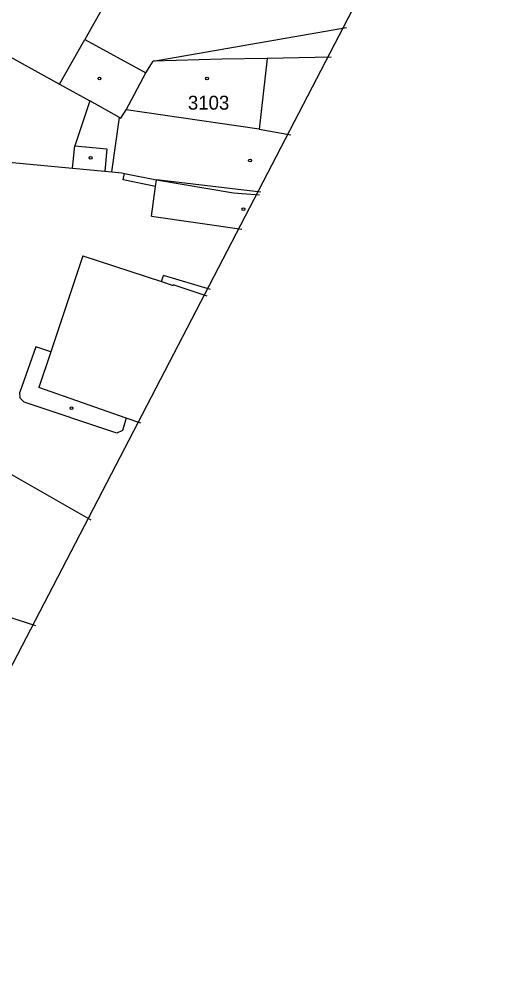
# Model space of a CAD drawing. Extents: x -781083 to -763634, y -1029516 to -1022695.
# Drawn here: x -764957.7 to -764898.4, y -1023999.1 to -1023880.9 of the extents above; entities that cross this region are included whole.
import ezdxf

# ---------------------------------------------------------------- set-up
doc = ezdxf.new("R2010")
doc.units = 0
for name, color, linetype in [('Hranice parcel', 7, 'Continuous'), ('Parcelní čísla', 7, 'Continuous'), ('Vnitřní kresba', 7, 'Continuous'), ('Vrstva 3', 7, 'Continuous'), ('Značky budov', 7, 'Continuous')]:
    doc.layers.add(name, color=color, linetype=linetype)

# ---------------------------------------------------------------- blocks, each defined once
blk = doc.blocks.new('4.02')
at = {"layer": 'Značky budov'}
blk.add_circle((-0.1, 0), 1.75, dxfattribs=at)

msp = doc.modelspace()

# ---------------------------------------------------------------- linework, layer by layer
msp.add_lwpolyline([(-765336.12, -1024363.48), (-765204.05, -1024432.09), (-764769.73, -1023596.11), (-764901.79, -1023527.49)], close=True)
at = {"layer": 'Hranice parcel'}
msp.add_line((-764941.38, -1023885.98), (-764917.77, -1023881.89), dxfattribs=at)
for points in [[(-764927.47, -1023885.67), (-764928.44, -1023894.28), (-764933.48, -1023893.55), (-764944.68, -1023891.94)], [(-764944.68, -1023891.94), (-764942.27, -1023887.42), (-764941.38, -1023885.98)], [(-764927.47, -1023885.67), (-764932.94, -1023885.75), (-764941.38, -1023885.98)], [(-764919.64, -1023885.49), (-764927.47, -1023885.67)], [(-764946.42, -1023899.52), (-764945.51, -1023892.86), (-764945.34, -1023892.96), (-764944.68, -1023891.94)], [(-764967.7, -1023897.5), (-764951.22, -1023899.07), (-764947.29, -1023899.44), (-764946.42, -1023899.52)], [(-764946.42, -1023899.52), (-764945.2, -1023899.64), (-764944.87, -1023899.7), (-764940.96, -1023900.48), (-764931.58, -1023902.07), (-764928.39, -1023902.32)]]:
    msp.add_lwpolyline(points, dxfattribs=at)
at = {"layer": 'Vnitřní kresba'}
for p, q in [((-764944.52, -1023874.04), (-764949.74, -1023883.33)), ((-764963.43, -1023882.91), (-764952.84, -1023888.79)), ((-764952.84, -1023888.79), (-764949.74, -1023883.33)), ((-764949.74, -1023883.33), (-764942.27, -1023887.42)), ((-764952.84, -1023888.79), (-764949.13, -1023890.85)), ((-764949.13, -1023890.85), (-764950.96, -1023896.34)), ((-764945.51, -1023892.86), (-764949.13, -1023890.85)), ((-764928.44, -1023894.28), (-764924.58, -1023894.99)), ((-764951.22, -1023899.07), (-764950.96, -1023896.34)), ((-764950.96, -1023896.34), (-764947.03, -1023896.71)), ((-764947.03, -1023896.71), (-764947.29, -1023899.44)), ((-764945.03, -1023900.49), (-764944.87, -1023899.7)), ((-764941.08, -1023901.29), (-764945.03, -1023900.49)), ((-764941.08, -1023901.29), (-764940.96, -1023900.48)), ((-764928.21, -1023901.99), (-764940.96, -1023900.48)), ((-764941.6, -1023904.9), (-764941.08, -1023901.29)), ((-764941.6, -1023904.9), (-764930.55, -1023906.49)), ((-764949.96, -1023909.77), (-764953.88, -1023921.5)), ((-764949.96, -1023909.77), (-764940.37, -1023912.91)), ((-764940.37, -1023912.91), (-764940.11, -1023912.17)), ((-764934.39, -1023913.88), (-764940.11, -1023912.17)), ((-764940.37, -1023912.91), (-764938.95, -1023913.37)), ((-764938.95, -1023913.37), (-764938.93, -1023913.29)), ((-764934.8, -1023914.67), (-764938.93, -1023913.29)), ((-764955.73, -1023920.88), (-764957.65, -1023926.39)), ((-764953.88, -1023921.5), (-764955.73, -1023920.88)), ((-764953.88, -1023921.5), (-764955.34, -1023925.85)), ((-764957.63, -1023927.14), (-764957.65, -1023926.39)), ((-764944.68, -1023929.57), (-764955.34, -1023925.85)), ((-764957.12, -1023927.64), (-764957.63, -1023927.14)), ((-764945.82, -1023931.42), (-764957.12, -1023927.64)), ((-764944.68, -1023929.57), (-764944.93, -1023930.39)), ((-764942.87, -1023930.2), (-764944.68, -1023929.57)), ((-764945.14, -1023931.09), (-764945.82, -1023931.42)), ((-764944.93, -1023930.39), (-764945.14, -1023931.09)), ((-764955.72, -1023954.94), (-764977.17, -1023948.14))]:
    msp.add_line(p, q, dxfattribs=at)
at = {"layer": 'Vrstva 3'}
msp.add_line((-764992.67, -1023917.22), (-764948.99, -1023941.98), dxfattribs=at)

# ---------------------------------------------------------------- block references
at = {"layer": 'Značky budov', "xscale": 0.1, "yscale": 0.10000000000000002}
for p in [(-764947.92, -1023888.1), (-764934.79, -1023888.11), (-764949.01, -1023897.8), (-764929.54, -1023898.12), (-764930.35, -1023904.06), (-764951.34, -1023928.37)]:
    msp.add_blockref('4.02', p, dxfattribs=at)

# ---------------------------------------------------------------- texts
at = {"layer": 'Parcelní čísla'}
msp.add_text('3103', height=1.7, dxfattribs=at).set_placement((-764937.14, -1023891.91))

doc.saveas('drawing.dxf')
